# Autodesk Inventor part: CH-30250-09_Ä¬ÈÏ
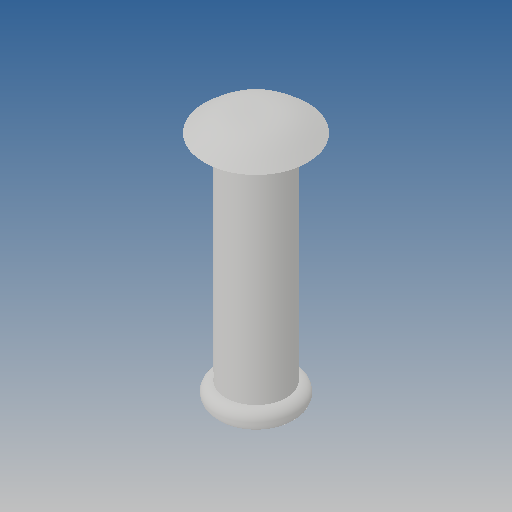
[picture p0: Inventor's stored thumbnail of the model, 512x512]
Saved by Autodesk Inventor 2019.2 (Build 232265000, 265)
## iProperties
Created: 2010-06
Part Number: CH-30250-09_Ä¬ÈÏ
Material: Ogólny
Document SubType Name: Modeling
Designer: CADENGINEERING4
Density: 1 g/cm^3
Appearance: Domyślna
Author: CADENGINEERING4
Revision Number: ÈÎºÎ
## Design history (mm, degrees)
feature "NONE"
node "Bryła1"
